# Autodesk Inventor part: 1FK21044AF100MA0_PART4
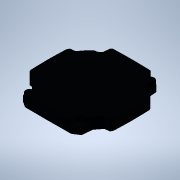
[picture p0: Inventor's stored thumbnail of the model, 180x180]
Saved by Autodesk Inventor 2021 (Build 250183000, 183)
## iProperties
Created: 2025-04
Part Number: 1FK21044AF100MA0_PART4
Material: Generic
Catalog Web Link: www.3dfindit.com
Description: -Servo synchronous motor
Document SubType Name: Modeling
Designer: psAdmin
Mass: 55.5405 g
Surface Area: 149.572 cm^2
Volume: 55.5405 cm^3
Density: 1 g/cm^3
Appearance: PSOLRGB-38-46-56
Category: PARTsolutions
Title: 1FK21044AF100MA0_PART4
Author: Cadenas PARTsolutions
Comments: Servo synchronous motor
Sending System: PARTsolutions
Preprocessor: ST-DEVELOPER v19.3
PSOL_IDENT_0: {$CADENAS_DATA/23d-libs/siemens_ag/_cat_/ec/e4/1fk21044af100ma0.prj},213 {VTYP=3D},{NB=1FK21044AF100
PSOL_IDENT_1: MA0_PART4},{LINA=1FK21044AF100MA0_PART4},{NN=1FK21044AF100MA0_PART4},{NOPRJ=TRUE},{DATE=19.08.2025 1
PSOL_IDENT_2: 4:01:05},{GEOMDATE=30.07.2025 02:01:01},{VERSION=},{LINEID=10},{WBVAR=},{WBNUMERIC=}  {NB=1FK21044AF
PSOL_IDENT_3: 100MA0_PART4},{LINA=1FK21044AF100MA0_PART4},{KT=DUMMY},{PREVIEW=../../../_pool_/cb/72/p_d211_xx_0043
PSOL_IDENT_4: 4j.png},{DESCSHORT=SIMOTICS S-1FK2 HD, SINAMICS S210 3AC 400V-480V, 1.27 Nm, 3000 rpm},{DESCLONG=SIM
PSOL_IDENT_5: OTICS S-1FK2 HD servo motor M0=1.27 Nm; PN = 0.4 kW at nN=3000 rpm (380-480 V); PN = 0.2 kW at nN=15
PSOL_IDENT_6: 00 rpm (200-240 V); with holding brake; degree of protection IP64; cylindrical shaft D19x40mm; absol
PSOL_IDENT_7: ute encoder 22-bit + 12-bit multiturn (encoder AM22DQC); with OCC interface; plug size M17, rotatabl
PSOL_IDENT_8: e; SIMOTICS S-1FK2 servomotorfor a wide range of uses in industrial environments. SIMOTICS S‑1FK2 se
PSOL_IDENT_9: rvomotors are compact synchronous motors with a high dynamic performance that set themselves apart a
PSOL_IDENT_10: s a result of their high power density, degree of protection and overload capability. The motors are
PSOL_IDENT_11: available in two variants: as High Dynamic variant (highest dynamic performance as a result of the
PSOL_IDENT_12: low intrinsic moment of inertia for applications demanding a high dynamic performance with low moved
PSOL_IDENT_13: masses) - and as Compact variant (precise and stable closed-loop control for medium up to large mov
PSOL_IDENT_14: ed masses as a result of a medium intrinsic moment of inertia). SIMOTICSS‑1FK2 servomotors fully exp
PSOL_IDENT_15: loit their strengths in a system with the SINAMICSS210 frequency converter and simple connection usi
PSOL_IDENT_16: ng the one cable connection (OCC). Advantages include the short control and positioning times, fast
PSOL_IDENT_17: and precise correction of disturbing quantities as well as stable control with a high dynamic perfor
PSOL_IDENT_18: mance. The servo motors can be configured to address a wide range of requirements. For example with
PSOL_IDENT_19: and without holding brake, IP64 or IP65 degree of protection, singleturn or multiturn absolute encod
PSOL_IDENT_20: ers - to name just a few. Further, the servomotors are available in different shaft heights extendin
PSOL_IDENT_21: g from 20 to 100. A shaft sealing ring is available to achieve an IP65 degree of protection and for
PSOL_IDENT_22: subsequent mounting at the motor or as spare part. SIMOTICS - the optimum motor for each and every m
PSOL_IDENT_23: otion control application.},{INTNO=195125043275},{SUPPLIERALTNO=1FK2104-4AF10-0MA0},{MANUID=1FK21044
PSOL_IDENT_24: AF100MA0},{MANUNAME=Siemens},{MANUTYPEDESC=Synchronous motor 1FK2-HD 1.27 NM},{AAU732=SIMOTICS},{AAO
PSOL_IDENT_25: 057=S-1FK2},{AAU734=SIMOTICS S-1FK2 HD servo motor M0=1.27 Nm; PN = 0.4 kW at nN=3000 rpm (380-480 V
PSOL_IDENT_26: ); PN = 0.2 kW at nN=1500 rpm (200-240 V); with holding brake; degree of protection IP64; cylindrica
PSOL_IDENT_27: l shaft D19x40mm; absolute encoder 22-bit + 12-bit multiturn (encoder AM22DQC); with OCC interface;
PSOL_IDENT_28: plug size M17, rotatable;},{AAW338=Synchronous motor 1FK2-HD 1.27 NM},{AAO742=SIMOTICS},{AAO663=4042
PSOL_IDENT_29: 948694015},{NOCUPEROU=1},{PRICEQUANTITY=1},{QUANTITYMIN=1},{QUANTITYINT=1},{CTN=85015100},{COO=DE},{
PSOL_IDENT_30: AAO676=1FK2104-4AF10-0MA0},{AAO677=Siemens AG},{ORDERUNIT=C62},{CONTENTUNIT=C62}
NB: 1FK21044AF100MA0_PART4
NT: Servo synchronous motor
NBSYN: $MANUID._PART4
LINA: 1FK21044AF100MA0_PART4
CATALOG: SIEMENS
PREVIEW: ../../../_pool_/cb/72/p_d211_xx_00434j.png
DESCSHORT: SIMOTICS S-1FK2 HD, SINAMICS S210 3AC 400V-480V, 1.27 Nm, 3000 rpm
DESCLONG: SIMOTICS S-1FK2 HD servo motor M0=1.27 Nm; PN = 0.4 kW at nN=3000 rpm (380-480 V); PN = 0.2 kW at nN=1500 rpm (200-240 V); with holding brake; degree of protect
INTNO: 195125043275
SUPPLIERALTNO: 1FK2104-4AF10-0MA0
MANUID: 1FK21044AF100MA0
MANUNAME: Siemens
MANUTYPEDESC: Synchronous motor 1FK2-HD 1.27 NM
AAU732: SIMOTICS
AAO057: S-1FK2
AAU734: SIMOTICS S-1FK2 HD servo motor M0=1.27 Nm; PN = 0.4 kW at nN=3000 rpm (380-480 V); PN = 0.2 kW at nN=1500 rpm (200-240 V); with holding brake; degree of protect
AAW338: Synchronous motor 1FK2-HD 1.27 NM
AAO742: SIMOTICS
AAO663: 4042948694015.0
NOCUPEROU: 1
PRICEQUANTITY: 1
QUANTITYMIN: 1
QUANTITYINT: 1
CTN: 85015100
COO: DE
ARTICLENO: 1FK21044AF100MA0_PART4
BOMINFO: 1FK21044AF100MA0_PART4
CREATOR: CADENAS GmbH
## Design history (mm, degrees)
feature "2025_04_17_15_33_01_0580"
body "Solid1"
